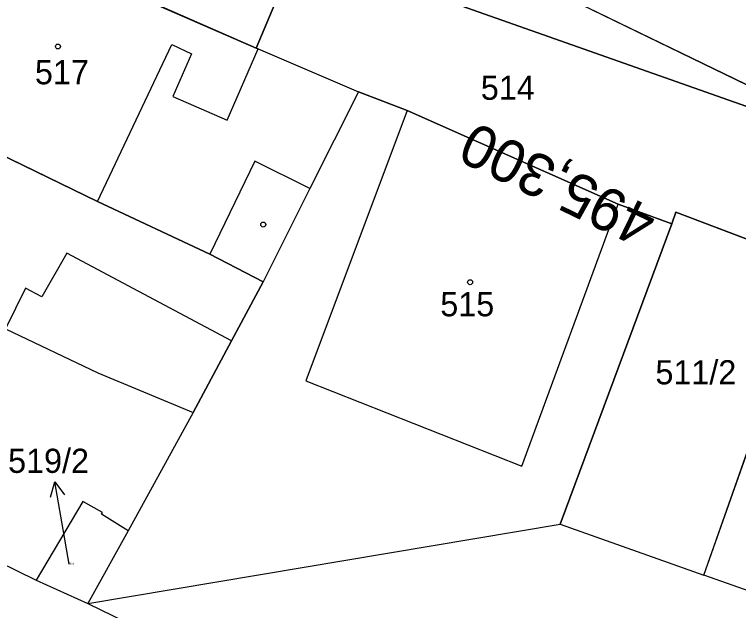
# Model space of a CAD drawing. Extents: x -762314 to -761449, y -993181 to -992589.
# Drawn here: x -761986.9 to -761936, y -992756.7 to -992714.8 of the extents above; entities that cross this region are included whole.
import ezdxf

# ---------------------------------------------------------------- set-up
doc = ezdxf.new("R2010")
doc.units = 0
for name, color, linetype in [('Formáty', 7, 'Continuous'), ('Hranice - vnitř_ kresba', 7, 'Continuous'), ('Hranice parcel', 7, 'Continuous'), ('Obvody jako plochy', 7, 'Continuous'), ('Parcelní čísla', 7, 'Continuous'), ('Prvky pro prodl_ par_ č_', 7, 'Continuous'), ('SO1010_osy_směrová a výšková úprava', 7, 'Continuous'), ('SO1010_staničení a hektometry', 7, 'Continuous'), ('Značky na budově ne v SPI', 7, 'Continuous'), ('Značky na budově v SPI', 7, 'Continuous')]:
    doc.layers.add(name, color=color, linetype=linetype)

msp = doc.modelspace()

# ---------------------------------------------------------------- linework, layer by layer
at = {"layer": 'Formáty'}
msp.add_lwpolyline([(-761558.019, -993180.938), (-762313.703, -992814.139), (-762204.471, -992589.097), (-761448.787, -992955.896)], close=True, dxfattribs=at)
msp.add_lwpolyline([(-761558.019, -993180.938), (-762313.703, -992814.139), (-762204.471, -992589.097), (-761448.787, -992955.896)], close=True, dxfattribs=at)
at = {"layer": 'Hranice - vnitř_ kresba'}
for p, q in [((-761981.055, -992727.916), (-761975.835, -992716.866)), ((-761975.835, -992716.866), (-761974.465, -992717.526)), ((-761971.955, -992722.196), (-761969.755, -992717.176)), ((-761974.465, -992717.526), (-761975.775, -992720.526)), ((-761975.775, -992720.526), (-761971.955, -992722.196)), ((-761959.285, -992721.516), (-761966.415, -992740.526)), ((-761969.995, -992725.086), (-761973.175, -992731.616)), ((-761966.135, -992727.006), (-761969.995, -992725.086)), ((-761951.215, -992746.546), (-761944.445, -992728.106)), ((-761983.215, -992731.546), (-761984.975, -992734.616)), ((-761971.635, -992737.726), (-761983.215, -992731.546)), ((-761986.135, -992734.016), (-761987.535, -992736.866)), ((-761984.975, -992734.616), (-761986.135, -992734.016)), ((-761966.415, -992740.526), (-761951.215, -992746.546))]:
    msp.add_line(p, q, dxfattribs=at)
at = {"layer": 'Hranice parcel'}
for p, q in [((-761964.966, -992705.349), (-761969.895, -992717.116)), ((-761958.745, -992712.976), (-761925.225, -992724.826)), ((-761969.895, -992717.116), (-761978.195, -992713.476)), ((-761969.895, -992717.116), (-761969.755, -992717.176)), ((-761969.755, -992717.176), (-761962.705, -992720.196)), ((-761962.705, -992720.196), (-761966.135, -992727.006)), ((-761959.285, -992721.516), (-761962.705, -992720.196)), ((-761944.445, -992728.106), (-761959.285, -992721.516)), ((-761981.055, -992727.916), (-761993.135, -992722.056)), ((-761966.135, -992727.006), (-761969.415, -992733.566)), ((-761973.175, -992731.616), (-761981.055, -992727.916)), ((-761940.665, -992729.476), (-761944.445, -992728.106)), ((-761940.385, -992728.676), (-761940.665, -992729.476)), ((-761928.225, -992733.286), (-761940.385, -992728.676)), ((-761948.525, -992750.636), (-761940.665, -992729.476)), ((-761969.415, -992733.566), (-761973.175, -992731.616)), ((-761971.635, -992737.726), (-761969.415, -992733.566)), ((-761987.535, -992736.866), (-761981.035, -992739.966)), ((-761974.325, -992742.766), (-761971.635, -992737.726)), ((-761938.425, -992754.206), (-761933.275, -992739.616)), ((-761981.035, -992739.966), (-761974.325, -992742.766)), ((-761974.325, -992742.766), (-761978.915, -992751.096)), ((-761982.095, -992749.036), (-761985.385, -992754.566)), ((-761980.715, -992749.796), (-761982.095, -992749.036)), ((-761980.775, -992749.916), (-761980.715, -992749.796)), ((-761978.915, -992751.096), (-761980.775, -992749.916)), ((-761981.735, -992756.216), (-761948.525, -992750.636)), ((-761948.525, -992750.636), (-761938.425, -992754.206)), ((-761978.915, -992751.096), (-761981.735, -992756.216)), ((-761991.085, -992751.766), (-761985.385, -992754.566)), ((-761985.385, -992754.566), (-761981.735, -992756.216)), ((-761909.235, -992764.506), (-761938.425, -992754.206)), ((-761981.735, -992756.216), (-761977.055, -992758.476))]:
    msp.add_line(p, q, dxfattribs=at)
at = {"layer": 'Obvody jako plochy'}
for p, q in [((-761924.679, -992724.904), (-761957.371, -992709.036)), ((-761924.679, -992724.904), (-761957.371, -992709.036)), ((-761958.745, -992712.976), (-761925.225, -992724.826)), ((-761969.895, -992717.116), (-761978.195, -992713.476)), ((-761981.055, -992727.916), (-761975.835, -992716.866)), ((-761975.835, -992716.866), (-761974.465, -992717.526)), ((-761971.955, -992722.196), (-761969.755, -992717.176)), ((-761969.895, -992717.116), (-761969.755, -992717.176)), ((-761974.465, -992717.526), (-761975.775, -992720.526)), ((-761975.775, -992720.526), (-761971.955, -992722.196)), ((-761959.285, -992721.516), (-761966.415, -992740.526)), ((-761944.445, -992728.106), (-761959.285, -992721.516)), ((-761981.055, -992727.916), (-761993.135, -992722.056)), ((-761981.055, -992727.916), (-761993.135, -992722.056)), ((-761973.175, -992731.616), (-761981.055, -992727.916)), ((-761951.215, -992746.546), (-761944.445, -992728.106)), ((-761983.215, -992731.546), (-761984.975, -992734.616)), ((-761971.635, -992737.726), (-761983.215, -992731.546)), ((-761969.415, -992733.566), (-761973.175, -992731.616)), ((-761971.635, -992737.726), (-761969.415, -992733.566)), ((-761986.135, -992734.016), (-761987.535, -992736.866)), ((-761984.975, -992734.616), (-761986.135, -992734.016)), ((-761938.425, -992754.206), (-761933.275, -992739.616)), ((-761966.415, -992740.526), (-761951.215, -992746.546)), ((-761909.235, -992764.506), (-761938.425, -992754.206))]:
    msp.add_line(p, q, dxfattribs=at)
for points in [[(-761981.358, -992697.393), (-761983.255, -992701.076), (-761987.155, -992709.556), (-761984.475, -992710.726), (-761978.195, -992713.476), (-761969.895, -992717.116), (-761964.966, -992705.349)], [(-761964.966, -992705.349), (-761969.895, -992717.116), (-761969.755, -992717.176), (-761962.705, -992720.196), (-761959.285, -992721.516), (-761944.445, -992728.106), (-761940.665, -992729.476), (-761940.385, -992728.676), (-761928.225, -992733.286), (-761925.465, -992725.506), (-761925.225, -992724.826), (-761958.745, -992712.976), (-761957.371, -992709.036)], [(-761957.371, -992709.036), (-761958.745, -992712.976), (-761925.225, -992724.826), (-761924.715, -992725.006), (-761924.679, -992724.904)], [(-761957.371, -992709.036), (-761958.745, -992712.976), (-761925.225, -992724.826), (-761924.715, -992725.006), (-761924.679, -992724.904)]]:
    msp.add_lwpolyline(points, dxfattribs=at)
for points in [[(-761969.895, -992717.116), (-761969.755, -992717.176), (-761962.705, -992720.196), (-761966.135, -992727.006), (-761969.415, -992733.566), (-761973.175, -992731.616), (-761981.055, -992727.916), (-761993.135, -992722.056), (-761987.155, -992709.556), (-761984.475, -992710.726), (-761978.195, -992713.476)], [(-761984.475, -992710.726), (-761987.155, -992709.556), (-761993.135, -992722.056), (-761981.055, -992727.916), (-761975.835, -992716.866), (-761974.465, -992717.526), (-761975.775, -992720.526), (-761971.955, -992722.196), (-761969.755, -992717.176), (-761969.895, -992717.116), (-761978.195, -992713.476)], [(-761978.915, -992751.096), (-761981.735, -992756.216), (-761948.525, -992750.636), (-761940.665, -992729.476), (-761944.445, -992728.106), (-761959.285, -992721.516), (-761962.705, -992720.196), (-761966.135, -992727.006), (-761969.415, -992733.566), (-761971.635, -992737.726), (-761974.325, -992742.766)], [(-761959.285, -992721.516), (-761966.415, -992740.526), (-761951.215, -992746.546), (-761944.445, -992728.106)], [(-761973.175, -992731.616), (-761981.055, -992727.916), (-761993.135, -992722.056), (-761997.785, -992731.756), (-761987.535, -992736.866), (-761981.035, -992739.966), (-761974.325, -992742.766), (-761971.635, -992737.726), (-761969.415, -992733.566)], [(-761971.635, -992737.726), (-761983.215, -992731.546), (-761984.975, -992734.616), (-761986.135, -992734.016), (-761987.535, -992736.866), (-761997.785, -992731.756), (-761993.135, -992722.056), (-761981.055, -992727.916), (-761973.175, -992731.616), (-761969.415, -992733.566)], [(-761898.855, -992743.476), (-761900.665, -992742.846), (-761928.225, -992733.286), (-761940.385, -992728.676), (-761940.665, -992729.476), (-761948.525, -992750.636), (-761938.425, -992754.206), (-761933.275, -992739.616), (-761903.225, -992750.236), (-761908.375, -992764.816), (-761907.285, -992765.196), (-761900.615, -992748.006)], [(-761933.275, -992739.616), (-761903.225, -992750.236), (-761908.375, -992764.816), (-761909.235, -992764.506), (-761938.425, -992754.206)], [(-761909.235, -992764.506), (-761938.425, -992754.206), (-761933.275, -992739.616), (-761903.225, -992750.236), (-761908.375, -992764.816)]]:
    msp.add_lwpolyline(points, close=True, dxfattribs=at)
at = {"layer": 'Prvky pro prodl_ par_ č_'}
for p, q in [((-761983.545, -992750.606), (-761984.054, -992747.649)), ((-761983.055, -992753.446), (-761983.545, -992750.606))]:
    msp.add_line(p, q, dxfattribs=at)
msp.add_lwpolyline([(-761984.377, -992748.72), (-761984.054, -992747.649), (-761983.392, -992748.55)], dxfattribs=at)
at = {"layer": 'Značky na budově ne v SPI'}
msp.add_circle((-761969.405, -992729.536), 0.175, dxfattribs=at)
at = {"layer": 'Značky na budově v SPI'}
for centre in [(-761983.845, -992717.006), (-761954.855, -992733.596)]:
    msp.add_circle(centre, 0.175, dxfattribs=at)

# ---------------------------------------------------------------- texts
at = {"layer": 'Parcelní čísla'}
for s, height, p in [('517', 1.7, (-761985.465, -992719.666)), ('514', 1.7, (-761954.105, -992720.756)), ('515', 1.7, (-761956.955, -992735.996)), ('511/2', 1.7, (-761941.825, -992740.786)), ('519/2', 0.1, (-761983.055, -992753.446))]:
    msp.add_text(s, height=height, dxfattribs=at).set_placement(p)
at = {"layer": 'Prvky pro prodl_ par_ č_'}
msp.add_text('519/2', height=1.7, dxfattribs=at).set_placement((-761987.352, -992747.016))
at = {"layer": 'SO1010_osy_směrová a výšková úprava'}
msp.add_text('495,300', height=3, rotation=154.1096, dxfattribs=at).set_placement((-761941.521, -992728.585))
at = {"layer": 'SO1010_staničení a hektometry'}
msp.add_text('495,300', height=3, rotation=154.1096, dxfattribs=at).set_placement((-761941.521, -992728.585))

doc.saveas('drawing.dxf')
